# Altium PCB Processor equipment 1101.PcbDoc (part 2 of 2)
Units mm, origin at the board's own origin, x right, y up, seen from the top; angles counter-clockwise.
Board outline 129 x 113 mm, 4 copper layers (Top Layer, Signal Layer 1, Signal Layer 2, Bottom Layer), stack 0.778 mm thick; 199 components, 116 nets, 557 pads, 191 vias.
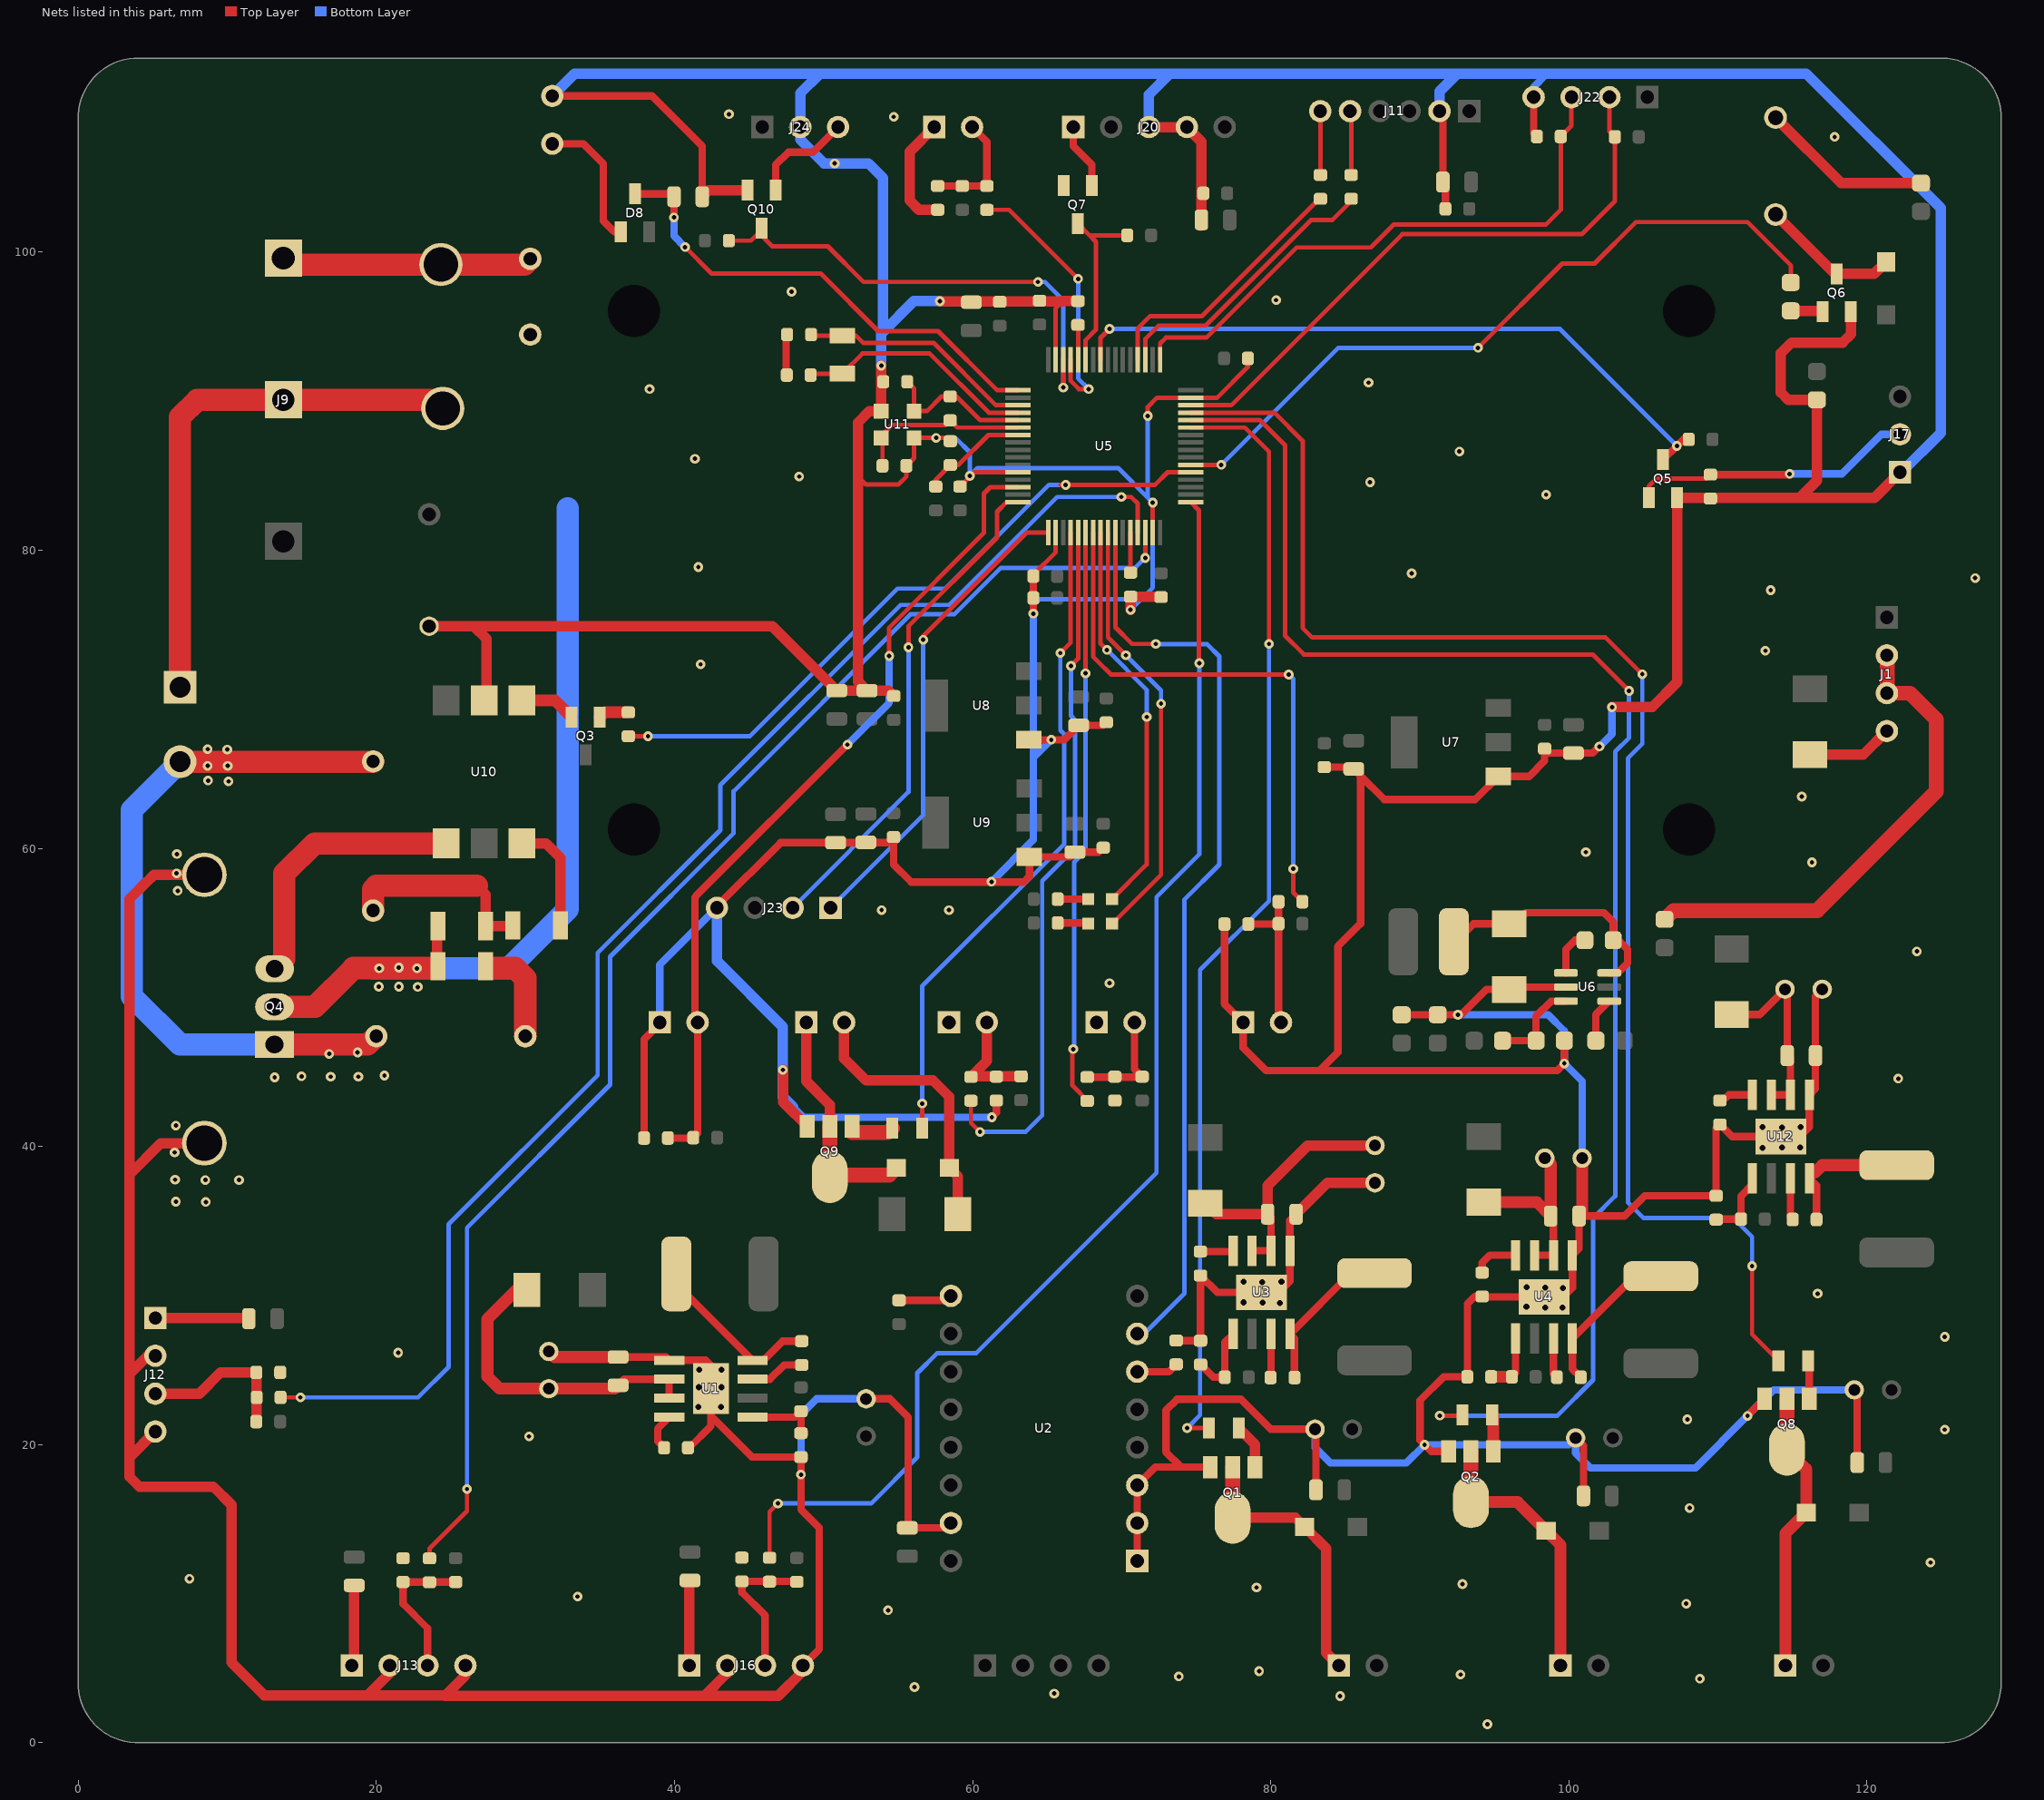
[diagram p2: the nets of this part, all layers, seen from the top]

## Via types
v1: diameter 0.65, hole 0.3, Top Layer to Bottom Layer, 163 vias
v2: diameter 0.65, hole 0.4, Top Layer to Bottom Layer, 24 vias
v3: diameter 3.4, hole 3, Top Layer to Bottom Layer, 4 vias

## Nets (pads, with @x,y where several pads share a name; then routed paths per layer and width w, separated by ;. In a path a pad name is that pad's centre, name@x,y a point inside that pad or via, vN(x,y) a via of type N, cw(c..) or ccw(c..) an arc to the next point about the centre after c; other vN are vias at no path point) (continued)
GND: C2.2 C3.1 C4.2 C5.1 C6.1 C8.2 C9.1 C10.1 C11.2 C12.1 C14.2 C15.1 C16.2 C17.1 C18.1 C20.1 C21.1 C22.2 C23.1 C24.1 C25.2 C26.2 C27.1 C28.1 C29.1 C30.1 C31.1 C32.1 C33.1 C34.1 C35.1 C36.1 C37.1 C38.1 C39.1 C40.1 C41.1 C42.2 C43.1 C44.1 C45.1 C46.1 C47.1 C48.1 C49.1 C50.1 C51.1 C52.1 C53.1 C54.1 C55.1 C56.1 C57.1 C58.2 C59.2 C61.2 C62.1 C63.1 C64.2 C65.1 C66.1 C67.2 CY1.1 D7.1 J1.2 J1.3 J4.1 J6.1 J7.1 J7.2 J8.2 J11.2 J12.2 J12.4 J13.2 J13.4 J14.1 J15.1 J16.2 J16.4 J17.1 J19.1 J20.3 J20.4 J22.4 J23.4 J24.2 Q1.1 Q2.1 Q5.2 Q6.2 Q7.2 Q8.1 Q9.1 Q10.2 R2.1 R3.2 R4.1 R9.1 R10.1 R14.1 R16.1 R17.1 R20.1 R21.2 R50.1 R51.1 R57.2 U1.0 U1.1 U2.1 U2.2 U2.3 U2.9 U2.15 U3.0 U3.1 U4.0 U4.1 U5.12 U5.18 U5.31 U5.47 U5.63 U6.2 U7.1 U8.1 U9.1 U10.2 U11.2 U11.4 U12.0 U12.1 | length 1009.8
  Top Layer w0.3: 52.324,84.912 52.832,84.404 55.016,84.404 55.56,84.948 C41.1@55.56,85.659 56.073,86.173 U11.4@56.073,87.528 v1(57.556,87.528) 58.288,87.528 C37.1@58.507,87.31 ; C43.1@59.157,84.264 60.116,85.224 U5.12@63.03,85.224 ; C44.1@64.072,78.257 64.072,78.346 65.58,79.855 U5.18@65.58,81.174 ; U5.63@65.58,92.774 65.58,96.223 66.055,96.698 66.065,96.708 ; v1(71.755,89.002) 71.755,89.611 72.367,90.224 U5.47@74.63,90.224 76.406,90.224 78.473,92.291 C46.1@78.473,92.862 ; U5.31@72.08,81.174 72.08,83.18 v1(72.085,83.185)
  Top Layer w0.5: 3.454,56.591 4.585,57.722 ; J7.2@8.788,58.22 J7.2@9.119,58.22 ; C4.2@31.572,26.249 C4.2@31.944,25.878 ; J8.2@31.801,110.464 38.507,110.464 41.869,107.102 C38.1@41.869,103.708 ; C5.1@36.22,25.878 39.426,25.878 U1.1@39.649,25.654 42.113,25.654 42.443,25.324 U1.0@42.443,23.749 42.443,21.92 ; C55.1@37.96,40.564 37.96,47.191 J14.1@39.014,48.245 ; R4.1@40.907,19.787 40.996,19.787 42.443,21.234 42.443,21.92 ; J23.4@42.85,56.007 42.85,56.109 47.117,60.376 C35.1@50.81,60.376 54.318,60.376 C30.1@54.697,60.755 54.697,58.918 55.88,57.734 63.424,57.734 63.815,58.126 U9.1@63.815,59.421 66.543,59.421 C34.1@66.863,59.741 68.466,59.741 C29.1@68.768,60.043 ; C39.1@47.485,94.488 47.485,91.796 C40.1@47.536,91.745 ; J16.4@48.619,5.182 49.708,6.271 49.708,14.427 48.489,15.646 v1(48.489,17.983) R2.1@48.489,19.164 45.199,19.164 42.443,21.92 ; C2.2@52.857,23.069 54.452,23.069 55.677,21.844 C3.1@55.677,14.412 ; C6.1@55.067,29.68 58.253,29.68 U2.9@58.545,29.972 ; C3.1@55.626,14.412 C3.1@55.677,14.412 ; U2.15@58.545,14.732 58.225,14.412 C3.1@55.677,14.412 ; v1(61.29,41.961) 61.595,42.266 C10.1@61.595,43.078 ; U8.1@63.765,67.281 66.148,67.281 C31.1@67.117,68.25 68.771,68.25 C27.1@68.971,68.451 ; v1(64.072,75.743) C48.1@64.072,76.797 C44.1@64.072,78.257 ; U2.1@71.045,12.192 U2.2@71.045,14.732 U2.3@71.045,17.272 72.261,18.488 73.994,18.488 ; R3.2@73.584,26.972 R9.1@75.296,26.972 75.286,26.983 R10.1@75.286,31.344 76.418,30.211 U3.0@79.385,30.211 80.528,30.211 81.29,30.973 U3.1@81.29,33.005 81.29,35.052 C12.1@81.697,35.458 ; Q1.1@75.945,18.488 73.994,18.488 ; C63.1@76.899,54.915 76.899,49.574 J19.1@78.152,48.321 78.152,46.613 79.68,45.085 83.287,45.085 ; C9.1@83.038,16.967 83.038,20.97 C8.2@82.976,21.031 80.01,21.031 78.003,23.038 73.711,23.038 72.974,22.301 72.974,19.507 73.994,18.488 ; C21.1@83.591,65.443 85.448,65.443 C24.1@85.573,65.319 86.03,64.861 ; C25.2@88.788,48.834 C26.2@91.201,48.834 v1(92.558,48.834) 92.776,48.834 94.473,50.531 D7.1@95.997,50.531 96.16,50.694 U6.2@99.807,50.694 ; J11.2@91.32,109.449 91.547,109.222 C52.1@91.547,104.699 91.72,104.526 C51.1@91.72,102.895 ; Q2.1@91.932,19.543 90.769,19.543 v1(90.322,19.99) 90.018,20.295 90.018,22.962 91.603,24.547 R14.1@93.19,24.547 93.19,29.436 93.688,29.934 R16.1@94.183,29.934 94.211,29.906 U4.0@98.334,29.906 99.629,29.906 100.239,30.516 U4.1@100.239,32.7 100.686,33.147 C17.1@100.686,35.331 ; J22.4@97.638,110.388 97.638,107.963 R57.2@97.854,107.747 ; R20.1@99.7,47.102 99.7,45.568 99.218,45.085 83.287,45.085 ; C14.2@100.452,20.447 100.98,19.918 C15.1@100.98,16.561 ; C17.1@100.889,35.535 C17.1@100.686,35.331 ; v1@102.045,66.84 101.59,66.385 C23.1@100.305,66.385 98.677,66.385 C20.1@98.374,66.688 98.374,65.862 97.329,64.817 U7.1@95.261,64.817 93.715,63.271 87.62,63.271 86.03,64.861 ; v1(111.986,21.92) Q8.1@113.129,23.063 ; C64.2@116.998,50.546 116.545,50.094 C65.1@116.545,46.101 116.545,43.876 U12.1@116.129,43.459 116.129,41.3 115.494,40.665 U12.0@114.224,40.665 110.947,40.665 R51.1@110.134,41.478 109.88,41.224 R50.1@109.88,36.69 105.092,36.69 103.734,35.331 C17.1@100.686,35.331 ; C61.2@119.146,23.673 119.344,23.474 C62.1@119.344,18.796 ; 83.287,45.085 84.506,46.304 84.506,53.416 86.03,54.94 86.03,64.861
  Top Layer w0.7: 4.572,57.734 3.454,56.617 3.454,56.591 3.454,38.125 ; 4.585,57.722 5.084,58.22 J7.2@8.469,58.22 J7.2@8.788,58.22 ; J12.4@5.182,20.875 3.454,19.147 ; J12.2@5.182,25.955 4.669,25.955 3.454,24.74 ; J7.1@9.119,40.22 J7.1@8.469,40.22 5.549,40.22 3.454,38.125 ; J13.2@20.898,5.182 20.898,4.667 19.406,3.175 ; CY1.1@23.546,74.9 26.548,74.9 ; J13.4@25.978,5.182 25.978,4.515 24.638,3.175 ; U10.2@27.229,69.926 27.407,70.103 27.407,74.041 26.548,74.9 ; C38.1@41.869,103.708 42.311,104.15 Q10.2@44.897,104.15 ; J16.2@43.539,5.182 43.539,4.677 42.012,3.15 ; v1@47.295,45.136 47.295,42.974 Q9.1@48.918,41.351 ; J16.4@48.619,5.182 48.619,4.804 46.965,3.15 42.012,3.15 ; v1(53.873,92.38) U11.2@53.873,89.328 53.083,89.328 52.324,88.57 52.324,84.912 52.324,71.175 C32.1@52.923,70.576 ; C28.1@54.712,70.218 54.354,70.576 C32.1@52.923,70.576 ; J6.1@57.429,108.382 55.778,106.731 55.778,103.454 56.401,102.832 C18.1@57.658,102.832 ; v1(57.81,96.698) 66.055,96.698 ; 66.065,96.708 R21.2@67.066,96.708 ; v1(70.597,75.997) R17.1@70.597,76.884 72.608,76.884 C45.1@72.644,76.848 ; J20.3@71.831,108.382 J20.4@74.371,108.382 75.352,107.402 C66.1@75.352,102.159 75.352,101.818 C66.1@75.286,101.752 ; C12.1@81.697,35.458 83.799,37.561 C11.2@86.995,37.561 ; v1(102.895,69.469) 105.588,69.469 107.264,71.145 Q5.2@107.264,83.515 115.494,83.515 ; Q6.2@118.918,95.987 118.918,94.483 118.364,93.929 114.935,93.929 114.224,93.218 114.224,90.576 114.717,90.084 C59.2@116.637,90.084 116.637,84.658 115.494,83.515 ; J17.1@122.21,85.224 120.501,83.515 115.494,83.515 ; 3.454,19.147 3.454,24.74 ; 3.454,19.147 3.454,17.831 4.101,17.185 9.054,17.185 10.287,15.951 10.287,5.385 12.497,3.175 19.406,3.175 ; 3.454,24.74 3.454,38.125 ; 19.406,3.175 24.638,3.175 ; 24.638,3.175 24.613,3.15 42.012,3.15 ; 26.548,74.9 46.568,74.9 C33.1@50.891,70.576 C32.1@52.923,70.576
  Top Layer w0.8: C4.2@31.944,25.878 C5.1@36.22,25.878 ; C17.1@100.889,35.535 C16.2@100.889,39.218
  Top Layer w1: C22.2@106.426,55.23 107.025,55.829 116.662,55.829 124.638,63.805 124.638,68.656 122.885,70.409 J1.3@121.488,70.409 ; J1.3@121.336,70.409 J1.3@121.488,70.409 ; J1.2@121.361,72.949 121.361,70.536 J1.3@121.488,70.409
  Bottom Layer w0.3: v1(57.556,87.528) 58.852,87.528 59.817,86.563 v1(59.817,84.988) 60.325,85.496 69.774,85.496 71.755,83.515 ; v1(64.072,75.743) 64.072,76.289 64.491,76.708 71.308,76.708 ; v1(70.597,75.997) 71.308,76.708 ; v1(71.755,89.002) 71.755,83.515 ; 71.308,76.708 72.085,77.485 v1(72.085,83.185) 71.755,83.515
  Bottom Layer w0.5: J14.1@39.014,48.245 J14.1@39.014,48.321 39.014,52.171 J23.4@42.85,56.007 J23.4@42.85,56.236 ; 47.968,42.634 48.641,41.961 v1(61.29,41.961) ; v1(48.489,17.983) 48.489,22.022 49.535,23.069 C2.2@52.857,23.069 ; v1(61.265,57.76) 64.072,60.566 64.072,66.078 ; v1(64.072,75.743) 64.072,66.078 ; v1(65.278,67.285) 64.072,66.078 ; C8.2@82.976,21.031 82.976,19.792 83.998,18.771 89.103,18.771 v1(90.322,19.99) 99.994,19.99 C14.2@100.452,20.447 100.452,19.436 101.448,18.44 108.506,18.44 v1(111.986,21.92) 113.738,23.673 C61.2@119.146,23.673 ; v1(92.558,48.834) 98.613,48.834 99.695,47.752 v1(99.695,45.568) 100.889,44.374 C16.2@100.889,39.218 ; J22.4@97.638,110.388 97.638,111.074 98.527,111.963 ; v1(102.057,66.827) 102.895,67.666 v1(102.895,69.469)
  Bottom Layer w0.7: J8.2@31.801,110.464 33.3,111.963 49.759,111.963 ; J23.4@42.85,56.007 42.85,52.451 47.269,48.031 v1(47.269,45.136) 47.269,43.332 47.968,42.634 ; v1(53.873,92.38) 53.873,94.524 54,94.651 ; v1@57.81,96.708 56.058,96.708 54,94.651 ; J20.3@71.831,108.382 71.831,110.566 73.228,111.963 ; J11.2@91.32,109.449 91.32,110.776 92.507,111.963 ; J17.1@122.21,85.224 122.308,85.224 124.943,87.859 124.943,102.946 115.926,111.963 98.527,111.963 92.507,111.963 ; 49.759,111.963 73.228,111.963 ; 49.759,111.963 48.438,110.642 J24.2@48.438,108.382 48.438,107.544 50.038,105.943 v1(50.749,105.943) 53.01,105.943 54,104.953 54,94.651 ; 73.228,111.963 92.507,111.963
  other v1: 94.539,1.245 84.658,3.124 65.481,3.302 56.109,3.734 108.788,4.293 73.838,4.445 92.735,4.572 79.223,4.801 54.331,8.89 107.874,9.322 33.503,9.804 79.045,10.414 92.862,10.643 7.468,10.998 124.257,12.09 108.102,15.748 30.251,20.549 125.222,21.006 107.95,21.692 21.463,26.162 125.222,27.229 116.688,30.124 8.56,36.271 6.553,36.297 8.534,37.744 10.795,37.744 6.502,37.77 6.477,39.599 6.553,41.402 122.098,44.552 69.19,50.952 123.342,53.086 53.899,55.855 58.42,55.855 6.68,57.15 6.604,58.318 116.307,59.055 6.629,59.614 101.143,59.741 115.621,63.475 41.758,72.339 113.182,73.254 113.538,77.318 127.254,78.13 89.459,78.435 41.605,78.867 98.476,83.718 86.665,84.557 48.362,84.938 41.377,86.131 92.659,86.614 38.329,90.805 86.563,91.237 80.366,96.774 47.854,97.333 117.831,107.721 54.712,109.068 43.663,109.245
  other v2: 41.605,22.53 43.129,22.53 41.631,23.851 43.155,23.851 41.656,25.019 43.155,25.019 98.425,29.185 99.568,29.185 97.155,29.261 80.62,29.489 79.451,29.515 78.181,29.54 99.593,30.505 98.425,30.531 97.18,30.556 79.426,30.886 80.721,30.912 78.181,30.937 113.005,39.903 114.3,39.929 115.519,39.929 114.3,41.275 113.005,41.3 115.545,41.3
HA: R44.1 U5.38 | length 49.4
  Top Layer w0.3: U5.38@74.63,85.724 v1(76.683,85.724) ; v1(93.904,93.574) 99.555,99.225 101.714,99.225 104.496,102.006 111.989,102.006 114.884,99.111 R44.1@114.884,97.953
  Bottom Layer w0.3: v1(76.683,85.724) 84.533,93.574 v1(93.904,93.574)
HD1: R23.2 U5.37 | length 45.4
  Top Layer w0.3: R23.2@36.906,67.521 v1(38.227,67.521) ; 65.913,84.379 v1(66.243,84.379) 72.238,84.379 73.082,85.224 U5.37@74.63,85.224
  Bottom Layer w0.3: v1(38.227,67.521) 45.068,67.521 54.966,77.419 58.166,77.419 65.126,84.379 v1(66.243,84.379)
IN1: Q5.3 R41.2 U5.57 | length 45.9
  Top Layer w0.3: U5.57@68.58,92.774 68.58,94.234 v1(69.19,94.844)
  Top Layer w0.5: Q5.3@106.314,86.065 v1(107.244,86.995) 107.676,87.427 R41.2@108.039,87.427
  Bottom Layer w0.3: v1(69.19,94.844) 99.395,94.844 v1(107.244,86.995)
IN2: Q10.3 R56.2 U5.62 | length 32.8
  Top Layer w0.3: R56.2@43.65,100.762 45.136,100.762 Q10.3@45.847,101.473 ; Q10.3@45.847,101.6 Q10.3@45.847,101.473 ; v1(64.389,97.993) 52.68,97.993 50.292,100.381 46.558,100.381 45.847,101.092 Q10.3@45.847,101.473 ; v1(66.08,90.907) U5.62@66.08,92.774
  Bottom Layer w0.3: v1(64.389,97.993) 64.861,97.993 66.08,96.774 v1(66.08,90.907)
IN3: Q7.3 R47.2 U5.59 | length 12.5
  Top Layer w0.3: Q7.3@67.056,101.905 67.843,101.117 ; U5.59@67.58,92.774 67.58,94.098 68.275,94.793 68.275,100.686 67.843,101.117 ; R47.2@70.371,101.117 67.843,101.117
K1: R36.1 U5.22 | length 39
  Top Layer w0.3: v1(66.751,46.533) 66.691,46.473 66.691,44.104 R36.1@67.78,43.015 ; v1(67.58,71.739) U5.22@67.58,81.174
  Bottom Layer w0.3: v1@66.802,46.533 66.802,59.055 67.58,59.833 v1(67.58,71.739)
K2: R48.1 U5.23 | length 38.1
  Top Layer w0.3: U5.23@68.08,81.174 68.08,72.865 68.809,72.136 ; 68.444,72.5 69.291,71.653 v1(81.204,71.653) ; v1(81.509,58.623) 81.509,57.031 R48.1@82.126,56.413
  Bottom Layer w0.3: v1(81.204,71.653) 81.509,71.349 v1(81.509,58.623)
K3: R52.1 U5.20 | length 44.3
  Top Layer w0.3: R52.1@56.617,41.224 v1(56.617,42.875) ; v1(65.888,73.101) 66.58,73.794 U5.20@66.58,81.174
  Bottom Layer w0.3: v1(56.617,42.875) 56.617,50.749 66.153,60.286 66.153,67.647 65.888,67.912 v1(65.888,73.101)
K5: R7.1 U5.21 | length 47.3
  Top Layer w0.3: R7.1@59.893,43.066 59.893,41.58 v1(60.503,40.97) ; v1(66.599,72.238) 67.08,72.719 U5.21@67.08,81.174
  Bottom Layer w0.3: v1(60.503,40.97) 63.551,40.97 64.668,42.088 64.668,57.81 66.878,60.02 66.878,68.605 66.599,68.885 v1(66.599,72.238)
K6: R15.1 U5.61 | length 18.6
  Top Layer w0.3: R15.1@60.96,102.832 62.446,102.832 v1(67.081,98.196) ; U5.61@66.58,92.774 66.58,91.357 67.132,90.805 v1(67.793,90.805)
  Bottom Layer w0.3: v1(67.081,98.196) 67.081,91.516 v1(67.793,90.805)
L: F1.1 J9.1 L5.1 | length 16.9
  Top Layer w1.5: J9.1@13.767,99.589 14.199,99.157 L5.1@24.333,99.157 29.947,99.157 F1.1@30.328,99.538
LED1: D14.2 U5.24 | length 26.8
  Top Layer w0.3: U5.24@68.58,81.174 68.58,73.736 v1(69.012,73.304) ; D14.2@69.355,56.591 71.679,58.915 v1(71.679,68.809)
  Bottom Layer w0.3: v1(69.012,73.304) 71.679,70.637 v1(71.679,68.809)
LED2: D15.2 U5.25 | length 29.1
  Top Layer w0.3: U5.25@69.08,81.174 69.08,74.151 v1(70.282,72.949) ; D15.2@69.355,54.94 72.644,58.23 v1(72.644,69.698) v1@72.695,69.748
  Bottom Layer w0.3: v1(70.282,72.949) 72.644,70.587 v1(72.644,69.698)
M1: R8.1 U5.43 | length 75.2
  Top Layer w0.3: v1(74.397,21.107) R8.1@75.851,21.107 ; U5.43@74.63,88.224 78.273,88.224 79.883,86.614 v1(79.883,73.711)
  Bottom Layer w0.3: v1(74.397,21.107) 75.26,21.971 75.26,51.841 79.883,56.464 v1(79.883,73.711)
M2: R13.1 U5.44 | length 104.7
  Top Layer w0.3: U5.44@74.63,88.724 79.272,88.724 80.975,87.02 80.975,74.244 82.22,73 101.6,73 v1(104.038,70.561) v1@104.038,70.358 ; v1(91.338,21.946) 92.793,21.946 R13.1@92.854,22.007
  Bottom Layer w0.3: v1@91.338,21.92 99.212,21.92 101.625,24.333 101.625,35.179 103.111,36.665 103.111,66.484 104.038,67.412 v1(104.038,70.561)
M3: R49.1 U5.45 | length 99.1
  Top Layer w0.3: U5.45@74.63,89.224 80.245,89.224 82.144,87.325 82.144,74.778 82.779,74.143 102.464,74.143 v1(104.927,71.679) ; v1(112.293,31.979) 112.293,27.388 R49.1@114.053,25.629
  Bottom Layer w0.3: v1(104.927,71.679) 104.927,67.005 103.962,66.04 103.962,36.246 105.016,35.192 111.036,35.192 112.293,33.934 v1(112.293,31.979)
N: J9.2 J10.1 N5.1 | length 36.5
  Top Layer w1.5: J10.1@6.833,70.807 6.833,88.925 7.997,90.089 J9.2@13.767,90.089 23.876,90.089 N5.1@24.46,89.505
NetC1_1: C1.1 U1.7 | length 3.7
  Top Layer w0.5: U1.7@45.237,24.384 46.406,24.384 47.358,25.337 C1.1@48.539,25.337
NetC1_2: C1.2 L1.2 U1.8 | length 11.9
  Top Layer w0.5: L1.2@40.56,31.775 40.56,30.332 U1.8@45.237,25.654 45.974,25.654 47.257,26.937 C1.2@48.539,26.937
NetC4_1: C4.1 C5.2 D1.2 U1.2 U1.3 | length 21.4
  Top Layer w0.5: D1.2@29.413,30.378 D1.2@30.099,30.378 ; C5.2@36.22,23.978 36.627,24.384 U1.2@39.649,24.384 U1.3@39.649,23.114
  Top Layer w0.8: D1.2@29.413,30.378 27.457,28.423 27.457,24.562 28.27,23.749 C4.1@31.572,23.749 35.992,23.749 C5.2@36.22,23.978
NetC7_1: C7.1 U3.7 | length 2.9
  Top Layer w0.5: C7.1@79.995,24.496 80.02,24.521 U3.7@80.02,27.417
NetC7_2: C7.2 L2.2 U3.8 | length 10.4
  Top Layer w0.5: C7.2@81.595,24.496 81.595,27.112 U3.8@81.29,27.417 85.377,31.504 L2.2@86.97,31.504
NetC10_2: C10.2 J4.2 R6.1 R7.2 | length 7.4
  Top Layer w0.7: R7.2@59.893,44.666 R7.2@59.931,44.704 ; J4.2@60.96,48.321 60.96,45.733 R7.2@59.931,44.704 ; R6.1@63.246,44.704 R7.2@59.931,44.704
NetC11_1: C11.1 C12.2 D4.2 U3.2 U3.3 | length 18.5
  Top Layer w0.5: U3.3@78.75,33.005 U3.2@80.02,33.005 80.02,35.235 C12.2@79.797,35.458
  Top Layer w0.7: D4.2@75.616,36.195 76.352,35.458 C12.2@79.797,35.458 79.797,37.379 82.479,40.061 C11.1@86.995,40.061
NetC13_1: C13.1 U4.7 | length 2.7
  Top Layer w0.5: U4.7@98.969,27.112 98.969,24.75 C13.1@99.197,24.521
NetC13_2: C13.2 L3.2 U4.8 | length 10.5
  Top Layer w0.5: C13.2@100.797,24.521 100.239,25.08 U4.8@100.239,27.112 104.423,31.297 L3.2@106.172,31.297
NetC16_1: C16.1 C17.2 D5.2 U4.2 U4.3 | length 12.9
  Top Layer w0.5: U4.3@97.699,32.7 U4.2@98.969,32.7 98.969,34.711 98.786,34.895 C17.2@98.786,35.331 ; C16.1@98.389,39.218 C16.1@98.786,38.821
  Top Layer w0.8: D5.2@94.285,36.265 97.852,36.265 C17.2@98.786,35.331 C16.1@98.786,38.821
NetC18_2: C18.2 J6.2 R12.1 R15.2 | length 7.7
  Top Layer w0.5: C18.2@57.658,104.432 R15.2@60.96,104.432 60.96,107.391 J6.2@59.969,108.382
NetC19_1: C19.1 D7.2 L4.1 U6.6 | length 16.6
  Top Layer w0.5: L4.1@92.289,53.731 92.39,53.731 93.59,54.931 D7.2@95.997,54.931 96.368,54.931 97.113,55.677 102.362,55.677 102.977,55.062 C19.1@102.977,53.833 103.317,53.833 103.937,53.213 103.937,52.299 103.282,51.644 U6.6@102.707,51.644
NetC19_2: C19.2 U6.1 | length 3.1
  Top Layer w0.5: U6.1@99.807,51.644 99.807,53.223 100.417,53.833 C19.2@101.077,53.833
NetC38_2: C38.2 D8.3 U5.1 | length 32.9
  Top Layer w0.3: v1@40.589,100.457 v1(40.716,100.33) 42.494,98.552 49.809,98.552 53.67,94.691 57.683,94.691 61.651,90.724 U5.1@63.03,90.724
  Top Layer w0.5: D8.3@37.348,103.896 39.782,103.896 C38.2@39.969,103.708 v1(39.969,102.321) v1@39.98,102.311
  Bottom Layer w0.5: v1(39.969,102.321) 39.969,101.077 v1(40.716,100.33)
NetC53_2: C53.2 J12.3 R28.1 R34.2 | length 10.7
  Top Layer w0.7: J12.3@5.182,23.415 8.124,23.415 9.55,24.841 C53.2@11.951,24.841 R28.1@11.951,21.539
NetC54_2: C54.2 J13.3 R29.1 R35.2 | length 9.8
  Top Layer w0.5: J13.3@23.438,5.182 23.438,7.677 21.793,9.322 C54.2@21.793,10.782 R29.1@25.324,10.782
NetC56_2: C56.2 J15.2 R33.1 R36.2 | length 7.5
  Top Layer w0.5: R36.2@67.691,44.653 71.349,44.653 R33.1@71.374,44.679 70.866,45.187 J15.2@70.866,48.321
NetC57_2: C57.2 J16.3 R39.1 R43.2 | length 10
  Top Layer w0.5: J16.3@46.079,5.182 46.079,8.531 44.526,10.084 C57.2@44.526,10.82 48.184,10.82 R39.1@48.209,10.795
NetC58_1: C58.1 J17.2 Q5.1 | length 19.1
  Top Layer w0.3: Q5.1@105.364,83.515 105.364,84.282 105.893,84.811 109.246,84.811 C58.1@109.499,85.064 ; v1@114.757,85.064 v1(114.808,85.115)
  Top Layer w0.5: C58.1@109.499,85.064 v1@114.757,85.064
  Bottom Layer w0.5: v1(114.808,85.115) 118.313,85.115 120.961,87.764 J17.2@122.21,87.764
NetC60_1: C60.1 U12.7 | length 2.8
  Top Layer w0.5: U12.7@114.859,37.871 114.859,35.255 C60.1@115.011,35.103
NetC60_2: C60.2 L6.2 U12.8 | length 9.2
  Top Layer w0.5: 116.497,38.24 U12.8@116.129,37.871 116.611,37.389 C60.2@116.611,35.103
  Top Layer w0.8: 116.497,38.24 117,38.743 L6.2@121.996,38.743
NetC63_2: C63.2 J19.2 R45.1 R48.2 | length 10.2
  Top Layer w0.5: C63.2@78.499,54.915 80.501,54.915 R45.1@80.526,54.94 ; R48.2@80.526,56.413 R45.1@80.526,54.94 ; J19.2@80.692,48.321 80.526,48.487 R45.1@80.526,54.94
NetC64_1: C64.1 C65.2 D10.2 U12.2 U12.3 | length 12.8
  Top Layer w0.5: D10.2@110.922,48.844 112.796,48.844 C64.1@114.498,50.546 114.645,50.398 C65.2@114.645,46.101 114.859,45.888 U12.2@114.859,43.459 U12.3@113.589,43.459
NetCX1_1: CX1.1 R24.2 R25.1 | length 13.3
  Top Layer w0.7: 26.746,57.48 27.33,56.896 R25.1@27.33,54.788 29.113,54.788 R24.2@29.159,54.834
  Top Layer w1.5: CX1.1@19.787,55.824 19.787,57.252 20.015,57.48 26.746,57.48
NetCX1_2: CX1.2 CX2.2 J10.2 Q4.1 | length 48
  Top Layer w1.5: J10.2@6.833,65.807 19.769,65.807 CX1.2@19.787,65.824 ; Q4.1@13.82,46.833 19.43,46.833 CX2.2@19.994,47.396
  Bottom Layer w1.5: J10.2@6.833,65.807 3.607,62.581 3.607,50.063 6.837,46.833 Q4.1@13.17,46.833 Q4.1@13.82,46.833
  other v1: 13.183,44.628 16.942,44.679 18.796,44.679 14.986,44.704 20.549,44.755 16.84,46.203 18.745,46.304 10.084,64.491 8.712,64.541 8.687,65.532 10.033,65.532 10.008,66.624 8.687,66.65
NetCX2_1: CX2.1 R27.1 | length 6.6
  Top Layer w1.5: R27.1@27.584,51.968 29.312,51.968 29.994,51.286 CX2.1@29.994,47.396
NetD2_1: D2.1 J1.4 | length 5.8
  Top Layer w0.7: D2.1@116.18,66.294 119.761,66.294 J1.4@121.336,67.869
NetD3_1: D3.1 J3.1 Q1.2 | length 15.3
  Top Layer w0.7: Q1.2@77.445,15.088 81.661,15.088 D3.1@82.271,14.478 83.718,13.03 83.718,6.039 J3.1@84.575,5.182
NetD6_1: D6.1 J5.1 Q2.2 | length 15.3
  Top Layer w0.8: Q2.2@93.432,16.143 96.557,16.143 D6.1@98.476,14.224 99.434,13.265 J5.1@99.434,5.182
NetD8_2: D8.2 J8.1 | length 9.3
  Top Layer w0.5: J8.1@31.801,107.264 33.883,107.264 35.23,105.918 35.23,102.083 35.966,101.346 D8.2@36.398,101.346
NetD9_1: D9.1 HA1.2 Q6.3 | length 9.4
  Top Layer w0.7: HA1.2@113.868,102.516 117.847,98.537 Q6.3@117.968,98.537 120.482,98.537 D9.1@121.285,99.339
NetD11_1: D11.1 J18.1 Q8.2 | length 15.6
  Top Layer w0.8: J18.1@114.522,5.182 114.522,14.04 D11.1@115.926,15.443 115.926,18.366 Q8.2@114.629,19.663
NetD12_2: D12.2 D13.2 J21.2 | length 18.6
  Top Layer w0.7: J21.2@51.384,48.321 51.384,45.898 52.857,44.425 57.347,44.425 58.445,43.326 D13.2@58.445,38.557 59.004,37.998 D12.2@59.004,35.458
NetD13_1: D13.1 J21.1 Q9.2 | length 13.7
  Top Layer w0.7: J21.1@48.844,48.321 48.844,44.374 50.419,42.799 50.419,40.183
  Top Layer w1: Q9.2@50.419,37.541 50.952,38.075 54.407,38.075 D13.1@54.889,38.557
NetD14_1: D14.1 R54.1 | length 2
  Top Layer w0.5: R54.1@65.71,56.591 D14.1@67.755,56.591
NetD15_1: D15.1 R55.1 | length 2.1
  Top Layer w0.5: R55.1@65.71,54.991 67.704,54.991 D15.1@67.755,54.94
NetF1_2: F1.2 Q4.2 R25.2 R27.2 | length 56.1
  Top Layer w0.7: R25.2@24.08,54.813 24.08,52.146 R27.2@24.13,52.095
  Top Layer w1.5: Q4.2@13.17,49.373 15.875,49.373 18.466,51.964 R27.2@23.851,51.964
  Bottom Layer w1.5: 19.761,51.943 v1(20.193,51.943) v1(22.733,51.943) 28.88,51.943 32.842,55.905 32.842,82.804
  other v1: 22.784,50.698 20.168,50.724 21.514,50.724 21.514,51.994
NetHA1_1: HA1.1 R42.2 | length 11.6
  Top Layer w0.7: HA1.1@113.868,109.016 118.266,104.618 R42.2@123.622,104.618
NetJ11_5: J11.5 R37.2 | length 4.3
  Top Layer w0.3: J11.5@85.32,109.449 85.395,109.373 R37.2@85.395,105.169
NetJ11_6: J11.6 R38.2 | length 4.3
  Top Layer w0.3: J11.6@83.32,109.449 83.337,109.431 R38.2@83.337,105.169
NetJ12_1: J12.1 R31.1 | length 6.3
  Top Layer w0.7: J12.1@5.182,28.495 11.399,28.495 R31.1@11.445,28.448
NetJ13_1: J13.1 R32.1 | length 5.4
  Top Layer w0.7: J13.1@18.358,5.182 18.517,5.341 R32.1@18.517,10.556
NetJ16_1: J16.1 R40.1 | length 5.8
  Top Layer w0.7: J16.1@40.999,5.182 40.999,10.697 R40.1@41.199,10.897
NetJ20_1: J20.1 Q7.1 | length 4.4
  Top Layer w0.5: J20.1@66.751,108.382 66.751,107.112 68.006,105.857 Q7.1@68.006,104.455
NetJ24_3: J24.3 Q10.1 | length 6.9
  Top Layer w0.5: Q10.1@46.797,104.15 46.797,105.852 47.638,106.693 49.289,106.693 J24.3@50.978,108.382
NetQ1_3: Q1.3 R8.2 | length 3.1
  Top Layer w0.7: R8.2@77.851,21.107 78.945,20.014 Q1.3@78.945,18.488
NetQ2_3: Q2.3 R13.2 | length 2.5
  Top Layer w0.8: R13.2@94.854,22.007 94.932,21.929 Q2.3@94.932,19.543
NetQ3_1: Q3.1 R23.1 | length 2
  Top Layer w0.8: Q3.1@34.996,68.804 35.314,69.121 R23.1@36.906,69.121
NetQ3_2: Q3.2 U10.1 | length 3.8
  Top Layer w0.8: U10.1@29.769,69.926 31.974,69.926 Q3.2@33.096,68.804
NetQ4_3: Q4.3 U10.4 | length 18.4
  Top Layer w1.5: Q4.3@13.18,51.913 13.83,52.563 13.83,58.305 15.85,60.326 U10.4@24.689,60.326
NetQ6_1: Q6.1 R44.2 | length 2.2
  Top Layer w0.7: R44.2@114.884,96.053 116.952,96.053 Q6.1@117.018,95.987
NetQ8_3: Q8.3 R49.2 | length 2.6
  Top Layer w0.5: R49.2@116.053,25.629 116.129,25.552 Q8.3@116.129,23.063
NetQ9_3: Q9.3 R52.2 | length 2.8
  Top Layer w1: Q9.3@51.919,40.941 54.334,40.941 R52.2@54.617,41.224
NetR1_1: R1.1 R2.2 U1.5 | length 4.9
  Top Layer w0.5: U1.5@45.237,21.844 48.095,21.844 R1.1@48.489,22.238 R2.2@48.489,20.764
NetR3_1: R3.1 U2.6 | length 2.8
  Top Layer w0.5: U2.6@71.045,24.892 73.165,24.892 R3.1@73.66,25.387
NetR4_2: R4.2 U1.4 | length 2.6
  Top Layer w0.5: R4.2@39.307,19.787 38.875,20.219 38.875,21.069 U1.4@39.649,21.844
NetR5_1: R5.1 R9.2 U3.5 | length 5.1
  Top Layer w0.5: R9.2@75.296,25.372 76.147,24.521 R5.1@76.922,24.521 76.922,26.858 U3.5@77.48,27.417
NetR10_2: R10.2 U3.4 | length 2.2
  Top Layer w0.5: R10.2@75.286,32.944 77.419,32.944 U3.4@77.48,33.005
NetR11_1: R11.1 R14.2 U4.5 | length 4.1
  Top Layer w0.5: R11.1@96.175,24.547 96.429,24.801 U4.5@96.429,27.112
  Top Layer w0.8: R14.2@94.79,24.547 R11.1@96.175,24.547
NetR16_2: R16.2 U4.4 | length 3.1
  Top Layer w0.5: R16.2@94.183,31.534 94.183,32.182 94.702,32.7 U4.4@96.429,32.7
NetR17_2: R17.2 U5.28 | length 2.7
  Top Layer w0.3: U5.28@70.58,81.174 70.597,81.157 R17.2@70.597,78.484
NetR18_2: R18.2 R20.2 U6.3 | length 6.3
  Top Layer w0.5: R18.2@95.55,47.092 97.79,47.092 R20.2@97.8,47.102 97.8,48.728 98.816,49.744 U6.3@99.807,49.744
NetR19_1: R19.1 U6.4 | length 3
  Top Layer w0.5: R19.1@101.814,47.102 101.814,48.85 U6.4@102.707,49.744
NetR21_1: R21.1 U5.60 | length 2.3
  Top Layer w0.3: R21.1@67.066,95.108 67.08,95.094 U5.60@67.08,92.774
NetR24_1: R24.1 U10.6 | length 7.5
  Top Layer w0.7: U10.6@29.769,60.326 31.393,60.326 32.359,59.36 R24.1@32.359,54.834
NetR46_1: R46.1 R50.2 U12.5 | length 4.7
  Top Layer w0.5: R50.2@109.88,35.09 109.918,35.128 R46.1@111.544,35.128 111.544,36.665 112.319,37.44 U12.5@112.319,37.871
NetR51_2: R51.2 U12.4 | length 2.3
  Top Layer w0.5: R51.2@110.134,43.078 110.337,43.078 110.719,43.459 U12.4@112.319,43.459
NRST: C37.2 R22.1 U5.7 | length 7.2
  Top Layer w0.3: R22.1@57.531,84.264 57.531,84.735 C37.2@58.507,85.71 59.048,85.71 61.062,87.724 U5.7@63.03,87.724
OSC1: C42.1 R26.2 U5.5 U11.1 | length 10.2
  Top Layer w0.3: C42.1@55.611,91.298 56.073,90.835 U11.1@56.073,89.328 56.943,89.328 57.925,90.31 R26.2@58.496,90.31 58.915,90.31 60.501,88.724 U5.5@63.03,88.724
OSC2: C41.2 R26.1 U5.6 U11.3 | length 11.8
  Top Layer w0.3: C41.2@53.96,85.659 53.96,87.442 U11.3@53.873,87.528 53.873,87.681 54.585,88.392 58.179,88.392 R26.1@58.496,88.71 58.982,88.224 U5.6@63.03,88.224
PC14: C39.2 U5.3 X1.2 | length 15.9
  Top Layer w0.3: C39.2@49.085,94.488 49.182,94.391 52.167,94.391 52.654,93.904 57.379,93.904 61.559,89.724 U5.3@63.03,89.724
PC15: C40.2 U5.4 X1.1 | length 16.3
  Top Layer w0.3: C40.2@49.073,91.567 49.347,91.841 X1.1@51.257,91.841 52.608,93.193 57.125,93.193 61.094,89.224 U5.4@63.03,89.224
RX1: R37.1 U5.51 | length 19.2
  Top Layer w0.3: U5.51@71.58,92.774 71.58,94.161 72.492,95.072 75.641,95.072 82.702,102.133 84.125,102.133 85.395,103.403 R37.1@85.395,103.569
STEP: U2.7 U5.26 | length 62.1
  Top Layer w0.3: U5.26@69.58,81.174 69.58,74.819 70.688,73.711 v1(72.288,73.711)
  Bottom Layer w0.3: U2.7@71.045,27.432 71.501,27.432 74.219,30.15 74.219,56.566 76.556,58.903 76.556,72.873 75.743,73.685 72.314,73.685 v1(72.288,73.711)
SWCLK: J22.3 R57.1 U5.49 | length 39.8
  Top Layer w0.3: U5.49@72.58,92.774 72.58,93.865 72.974,94.259 75.692,94.259 81.737,100.305 86.716,100.305 88.24,101.829 98.45,101.829 99.454,102.832 R57.1@99.454,107.747 ; R57.1@99.454,108.039 R57.1@99.454,107.747 ; J22.3@100.178,110.388 100.178,108.471 R57.1@99.454,107.747
SWDIO: J22.2 R53.2 U5.46 | length 41.3
  Top Layer w0.3: U5.46@74.63,89.724 77.354,89.724 88.824,101.194 100.863,101.194 103.086,103.416 R53.2@103.086,107.721 102.718,108.09 J22.2@102.718,110.388
TEMP: C55.2 J14.2 R30.1 U5.14 | length 56.1
  Top Layer w0.3: v1(54.407,72.898) 54.407,74.803 60.757,81.153 60.757,83.795 61.186,84.224 U5.14@63.03,84.224
  Top Layer w0.5: C55.2@39.56,40.564 R30.1@41.262,40.564 ; R30.1@41.262,40.589 41.554,40.881 J14.2@41.554,48.245 ; J14.2@41.262,47.953 J14.2@41.554,48.245 ; J14.2@41.377,48.422 J14.2@41.554,48.245 ; 41.377,56.718 41.377,48.498 J14.2@41.554,48.321 J14.2@41.554,48.245 ; 41.45,56.791 v1(51.613,66.954)
  Bottom Layer w0.5: v1(51.613,66.954) 54.407,69.748 v1(54.407,72.898)
TX1: R38.1 U5.52 | length 18
  Top Layer w0.3: U5.52@71.08,92.774 71.08,94.88 71.882,95.682 75.362,95.682 83.249,103.569 R38.1@83.337,103.569
UART_RX: J23.1 U5.17 | length 32.1
  Top Layer w0.3: v1(56.693,73.99) 56.693,74.244 63.622,81.174 U5.17@65.08,81.174
  Bottom Layer w0.3: J23.1@50.47,56.007 56.693,62.23 v1(56.693,73.99)
UART_TX: J23.2 U5.16 | length 33.9
  Top Layer w0.3: v1(55.702,73.482) 55.702,74.905 61.646,80.848 61.646,82.575 62.294,83.224 U5.16@63.03,83.224
  Bottom Layer w0.3: J23.2@47.93,56.007 55.702,63.779 v1(55.702,73.482)
עˮK3: R35.1 U5.30 | length 95.7
  Top Layer w0.3: R35.1@23.571,12.37 23.571,13.03 26.086,15.545 v1(26.086,17.018) ; v1(71.58,79.479) U5.30@71.58,81.174
  Bottom Layer w0.3: v1(26.086,17.018) 26.086,34.544 35.687,44.145 35.687,52.73 43.967,61.011 43.967,63.83 55.829,75.692 58.776,75.692 61.9,78.816 70.917,78.816 v1(71.58,79.479)
出杯K4: R43.1 U5.33 | length 88.2
  Top Layer w0.3: R43.1@46.38,12.408 46.38,15.494 v1(46.939,16.053) ; U5.33@74.63,83.224 75.184,82.67 75.184,72.441 v1(75.209,72.415)
  Bottom Layer w0.3: v1(46.939,16.053) 53.188,16.053 56.286,19.152 56.286,24.79 57.633,26.137 60.249,26.137 72.339,38.227 72.339,56.718 75.209,59.588 v1(75.209,72.415)
落杯K2: R34.1 U5.29 | length 96.8
  Top Layer w0.3: R34.1@13.576,23.165 v1(14.91,23.165) ; v1(69.977,83.566) 70.637,83.566 71.08,83.123 U5.29@71.08,81.174
  Bottom Layer w0.3: v1(14.91,23.165) 22.809,23.165 24.854,25.209 24.854,34.785 34.849,44.78 34.849,52.984 43.078,61.214 43.078,64.237 55.169,76.327 58.445,76.327 65.684,83.566 v1(69.977,83.566)
pads on no net: COM1.1 COM1.2 COM1.3 COM1.4 J11.3 J11.4 U1.6 U2.4 U2.5 U3.6 U4.6 U5.2 U5.8 U5.9 U5.10 U5.11 U5.15 U5.27 U5.34 U5.35 U5.36 U5.39 U5.40 U5.42 U5.50 U5.53 U5.54 U5.55 U5.56 U5.58 U10.3 U10.5 U12.6
copper on no net: | length 0.3
  Top Layer w0.3: 59.314,94.92 59.324,94.91 59.51,94.724
  other v3: 3.5,3.5 125.5,3.5 3.5,109.5 125.5,109.5

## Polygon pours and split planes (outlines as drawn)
GND on Top Layer "Bottom Layer-No Net" (solid, remove dead copper, pour order 2): 26.695,120.98 26.695,118.593 29.007,116.281 30.251,115.037 30.251,105.74 34.9,105.74 34.9,105.334 34.9,95.834 36.093,94.64 37.998,92.735 37.998,55.829 37.998,42.672 34.468,39.141 33.249,37.922 -3.988,37.922 -3.988,27.838 -4.597,27.229 -2.616,25.248 -2.616,-8.839 22.225,-8.839 22.606,-9.22 25.654,-6.172 141.834,-6.172 141.834,17.069 145.364,20.599 139.497,26.467 139.497,118.339 29.261,118.339 26.314,121.285
GND on Bottom Layer "Bottom Layer-No Net" (solid, remove dead copper, pour order 4): 26.695,118.593 30.251,115.037 30.251,105.74 34.9,105.74 34.9,95.834 37.998,92.735 37.998,42.672 33.249,37.922 -4.013,37.922 -4.013,-9.322 -2.769,-10.566 -0.127,-7.925 39.903,-7.925 142.926,-7.925 144.932,-5.918 140.741,-1.727 140.741,126.848 35.052,126.848 26.772,118.567

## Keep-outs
Keep-Out Layer:
  lines w0.254: 0,4.112 0,108.882 ; 0.004,4.112 ccw(c3.998,3.991) 3.807,0 124.852,0 ccw(c124.998,4) 129,4.039 129,108.917 ; 0.009,108.882 cw(c3.999,109.009) 4.089,113 125.063,113 cw(c125.005,109) 129.004,108.917

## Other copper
Top Layer:
  region net L: 31.953,97.13 32.36,97.536 32.36,101.778 31.826,102.311 4.648,102.311 3.962,101.524 3.962,101.422 3.962,97.714 4.547,97.13
  region net NetR24_1: 29.388,61.366 32.055,61.366 33.731,59.69 33.731,53.899 33.426,53.594 31.801,53.594 31.801,58.496 30.912,59.385 29.388,59.385
  region net GND: 10.49,56.312 11.328,57.15 11.328,59.715 10.82,60.223 4.318,60.223 1.549,57.455 1.549,37.414 3.175,35.789 10.363,35.789 11.989,37.414 11.989,41.453 11.379,42.062 5.537,42.062 4.648,42.951 4.648,55.677 5.283,56.312
  region net NetF1_2: 17.932,52.502 18.745,53.315 21.869,53.315
  region net NetF1_2: 17.145,49.606 17.247,49.708 24.435,49.708 24.841,50.114 24.841,55.982 23.368,55.982 23.368,53.873 22.835,53.34 18.948,53.162 17.247,51.46 16.459,49.555
  region net NetF1_2: 24.841,55.982 23.901,55.982 20.371,52.451 20.858,51.964 23.851,51.964
  region net NetCX1_2: 12.522,47.727 16.662,47.727 17.551,48.616 21.057,48.616 21.692,47.981 21.692,44.856 20.523,43.688 12.522,43.688
  region net NetC60_2: 116.586,34.62 116.942,34.62 117.17,34.849 117.17,35.535 116.967,35.331 116.738,35.331
  region net NetC60_2: 116.865,34.798 116.865,34.95 117.17,35.255 117.17,37.287 117.475,37.592 124.46,37.592 124.816,37.948 124.816,39.903 124.562,40.157 117.729,40.157 116.103,38.532 116.103,34.747 116.23,34.62 116.942,34.62 117.17,34.849 117.17,35.281
  region net NetC13_2: 101.803,27.432 103.937,29.566 103.937,29.591 108.788,29.591 109.347,30.15 109.347,31.14 109.169,31.318 108.382,30.531 103.657,30.531
  region net NetC13_2: 103.632,29.566 103.937,29.87 108.636,29.87 109.347,30.582 109.347,32.385 108.661,33.071 103.454,33.071 101.956,31.572 101.956,29.235 100.711,27.991 99.974,27.991 99.974,26.492 99.898,26.416 100.051,26.264 100.051,25.268 101.163,24.155 101.473,24.155 101.803,24.486 101.803,27.432 104.242,29.87 106.197,29.87
  region net NetCX2_1: 26.924,52.705 26.975,52.756 31.14,52.756 32.512,51.384 32.512,46.025 31.902,45.415 27.94,45.415 26.848,46.507 26.848,52.781
  region net NetCX1_2: 5.309,64.948 5.309,66.65 5.766,67.107 20.853,67.107 21.463,66.497 21.463,64.795 20.676,64.008 6.248,64.008
  region net NetCX1_2: 5.41,65.786 5.842,66.294 5.766,67.107 20.853,67.107 21.463,66.497 21.463,64.795 20.676,64.008 6.248,64.008 5.309,64.948 5.309,66.65 5.766,67.107
  region net NetCX1_1: 18.644,54.991 18.009,55.626 18.009,57.404 18.872,58.268 29.007,58.268 29.997,57.277 29.997,54.229 29.591,53.823 26.873,53.823 26.772,53.924 26.797,53.95 26.797,56.413 26.213,56.998 25.959,56.744 21.361,56.744 19.609,54.991
  region net EARTH: 11.354,82.271 13.335,84.252 26.238,84.252 27.508,82.982 27.508,81.356 26.594,80.442 17.45,80.442 16.51,79.502 16.51,78.308 11.684,78.308 11.354,78.638
  region net N: 8.814,69.444 8.484,69.113 3.962,69.113 3.962,90.856 6.96,93.853 25.527,93.853 27.788,91.592 27.788,87.986 26.391,86.589 10.566,86.589 8.814,84.836
  region net L: 10.973,99.822 10.973,100.99 12.294,102.311 31.115,102.311 32.36,101.067 32.36,98.654 30.836,97.13 11.735,97.13 10.922,97.942 10.922,101.016
  region net NetCX1_1: 18.644,54.991 20.422,54.991 22.454,57.023 22.428,57.048 19.126,57.048
Bottom Layer:
  region net NetF1_2: 31.953,95.682 33.858,93.777 33.858,91.465 32.004,89.611 31.623,89.992 31.09,89.992
  region net NetF1_2: 28.981,95.682 31.953,95.682 31.953,93.624 33.858,91.719 33.858,54.712 29.007,49.86 19.279,49.86 18.288,50.851 18.288,52.857 18.771,53.34 27.864,53.34 31.344,56.82 31.344,81.966 30.163,83.147 30.163,92.291 28.981,93.472
  region net NetCX1_2: 10.643,67.107 3.962,67.107 1.524,64.668 1.524,47.574 5.41,43.688 20.523,43.688 21.692,44.856 21.692,47.981 21.057,48.616 17.551,48.616 16.713,47.777 7.417,47.777 4.75,50.444 4.75,62.23 6.528,64.008 10.643,64.008

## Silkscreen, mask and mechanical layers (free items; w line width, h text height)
Top Overlay:
  text "GND" at 31.115,112.039 h0.6
  text "5V" at 45.339,111.963 h0.7
  text "TX1" at 82.398,111.963 h0.7
  text "RX1" at 84.658,111.963 h0.7
  text "GND" at 90.348,111.963 h0.7
  text "5V" at 92.913,111.963 h0.7
  text "CLK" at 99.212,111.963 h0.7
  text "DIO" at 101.981,111.963 h0.7
  text "3V3" at 104.521,111.963 h0.7
  text "GND" at 47.676,111.938 h0.7
  text "IO" at 50.698,111.938 h0.7
  text "K6" at 59.436,111.938 h0.7
  text "GND" at 96.444,111.938 h0.7
  text "GND" at 56.413,111.912 h0.7
  text "5V" at 68.758,111.912 h0.7
  text "GND" at 70.993,111.912 h0.7
  text "GND" at 73.533,111.912 h0.7
  text "5V" at 76.556,111.912 h0.7
  text "IO" at 66.167,111.887 h0.7
  text "VBAT+" at 30.683,104.978 h0.6
  text "L" at 18.364,100.635 h1.5 r270
  text "N" at 18.415,91.059 h1.5 r270
  text "5V" at 125.527,91.059 h0.8 r270
  text "IO" at 125.527,88.468 h0.8 r270
  text "GND" at 125.501,86.258 h0.8 r270
  text "GND" at 18.466,81.89 h1.3 r270
  text "24V" at 125.527,77.267 h0.8 r270
  text "GND" at 125.527,73.965 h0.8 r270
  text "N1" at 0.533,71.196 h0.8 r270
  text "GND" at 125.527,71.044 h0.8 r270
  text "5V" at 125.527,67.666 h0.8 r270
  text "L1" at 0.508,66.421 h0.8 r270
  text "RX" at 50.038,57.556 h0.6
  text "3V3" at 44.653,57.531 h0.6
  text "TX" at 47.473,57.531 h0.6
  text "GND" at 42.037,57.506 h0.6
  text "GND" at 38.049,52.121 h0.6
  text "TEMP" at 40.589,52.121 h0.6
  text "V1+" at 50.597,51.943 h0.8
  text "K5" at 60.477,51.943 h0.6
  text "GND" at 67.462,51.943 h0.6
  text "K2" at 80.569,51.943 h0.6
  text "V1-" at 47.6,51.918 h0.8
  text "K1" at 70.587,51.918 h0.6
  text "GND" at 57.633,51.892 h0.6
  text "GND" at 77.114,51.892 h0.6
  text "1.5V" at 0.965,30.683 h0.8 r270
  text "GND" at 0.991,27.305 h0.8 r270
  text "WK2" at 0.965,24.486 h0.8 r270
  text "GND" at 0.965,21.615 h0.8 r270
  text "V3-" at 98.527,1.397 h0.8
  text "1.5V" at 16.459,1.346 h0.8
  text "GND" at 19.939,1.346 h0.8
  text "WK3" at 22.835,1.346 h0.8
  text "GND" at 25.781,1.346 h0.8
  text "V3+" at 101.473,1.346 h0.8
  text "GND" at 48.641,1.321 h0.8
  text "V2-" at 83.591,1.321 h0.8
  text "V2+" at 86.589,1.321 h0.8
  text "1.5V" at 39.116,1.295 h0.8
  text "GND" at 42.621,1.295 h0.8
  text "WK4" at 45.618,1.295 h0.8
  text "A1+" at 59.817,1.295 h0.8
  text "B1-" at 68.377,1.295 h0.8
  text "V4-" at 113.563,1.295 h0.8
  text "A1-" at 62.662,1.27 h0.8
  text "B1+" at 65.532,1.27 h0.8
  text "V4+" at 116.865,1.27 h0.8
Bottom Overlay:
  circle w0.254: c108.069,61.259 r3.5
  circle w0.254: c37.269,61.259 r3.5
  circle w0.254: c108.069,96.059 r3.5
  circle w0.254: c37.269,96.059 r3.5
